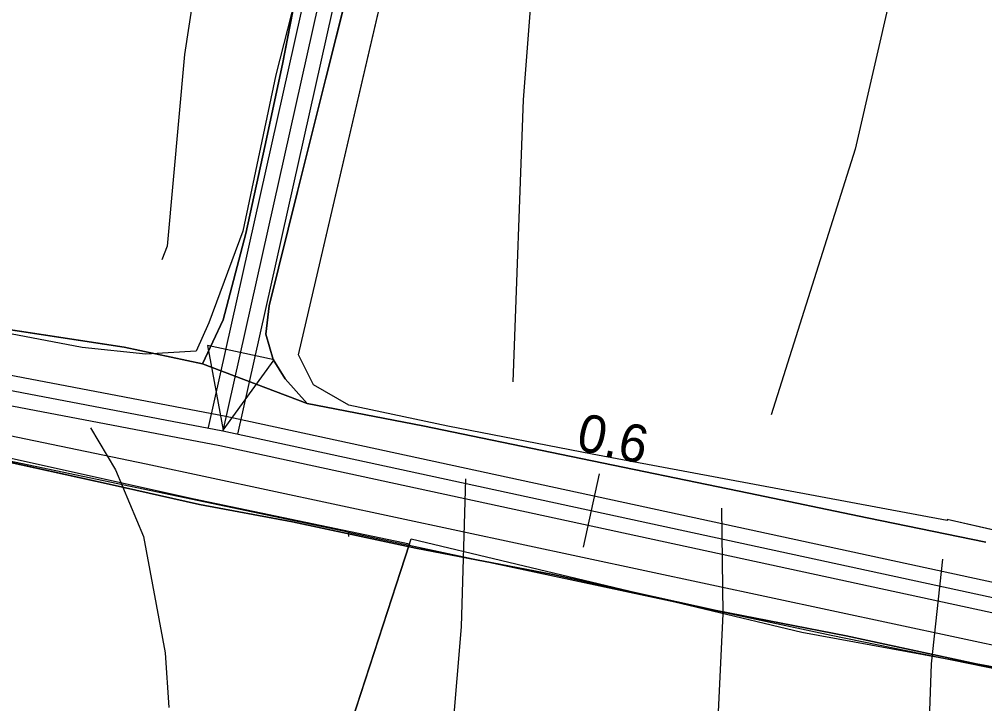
# Model space of a CAD drawing. Extents: x -662620 to -656370, y -1067090 to -1062990.
# Drawn here: x -658567.2 to -658438.7, y -1066109.2 to -1066018.1 of the extents above; entities that cross this region are included whole.
import ezdxf

# ---------------------------------------------------------------- set-up
doc = ezdxf.new("R2010")
doc.units = 0
for name, color, linetype in [('Agrotechnicka_opatreni_hrazkovani_a_dulkovani__mulcovani', 7, 'Continuous'), ('Default', 7, 'Continuous'), ('KRAJINNÁ_ZELEŇ_-_LINIOVÁ_-_STAV', 7, 'Continuous'), ('Organizacni_opatreni_ochranne_zatravnení__protierozni_rozmistovani_plodin__osevni_postup__stridani_plodin', 7, 'Continuous'), ('ORNÁ_PŮDA_-_STÁVAJÍCÍ', 7, 'Continuous'), ('OSTATNÍ_PLOCHA_-_STÁVAJÍCÍ', 7, 'Continuous'), ('OVOCNÝ_SAD_-_NAVRŽENÝ', 7, 'Continuous'), ('POLNÍ_CESTA_STÁVAJÍCÍ_-_KRAJ', 7, 'Continuous'), ('POLNÍ_CESTA_STÁVAJÍCÍ_-_OSA', 7, 'Continuous'), ('Popis_objektú_polních_cest_stávajících', 7, 'Continuous'), ('SDELOVACÍ_VEDENÍ_-_PODZEMNÍ', 7, 'Continuous'), ('VRSTEVNICE_ZDŮRAZNĚNÁ', 7, 'Continuous'), ('VRSTEVNICE_ZÁKLADNÍ', 7, 'Continuous')]:
    doc.layers.add(name, color=color, linetype=linetype)

msp = doc.modelspace()

# ---------------------------------------------------------------- linework, layer by layer
at = {"layer": 'Agrotechnicka_opatreni_hrazkovani_a_dulkovani__mulcovani'}
msp.add_lwpolyline([(-658454.8, -1065610.1), (-658459, -1065660.6), (-658461.7, -1065689.2), (-658464.3, -1065724.3), (-658468.4, -1065749), (-658474.4, -1065783.9), (-658495.1, -1065872.9), (-658497.1, -1065881.9), (-658511.2, -1065934.8), (-658524.2, -1065990.5), (-658533.1, -1066025.5), (-658537.5, -1066046.3), (-658542, -1066058.5), (-658543.7, -1066062.3), (-658550.4, -1066062.7), (-658558.89, -1066061.79), (-658593.12, -1066055.27), (-658662.77, -1066041.21), (-658696.34, -1066031.17)], dxfattribs=at)
at = {"layer": 'KRAJINNÁ_ZELEŇ_-_LINIOVÁ_-_STAV'}
msp.add_lwpolyline([(-658959.05, -1065783.35), (-658947.24, -1065797.56), (-658872.02, -1065915.68), (-658813.56, -1065971.96), (-658731.02, -1066028.63), (-658683.86, -1066049.55), (-658550.37, -1066077.32), (-658326.35, -1066125.24), (-658216.95, -1066151.9)], dxfattribs=at)
at = {"layer": 'Organizacni_opatreni_ochranne_zatravnení__protierozni_rozmistovani_plodin__osevni_postup__stridani_plodin'}
for points in [[(-658515.32, -1066087.97), (-658611.96, -1066385.11), (-658646.2, -1066373.85), (-658701.92, -1066378.35), (-658721.2, -1066377.7), (-658762.8, -1066380.1), (-658798.28, -1066383.49), (-658790.2, -1066369.8), (-658772.2, -1066340.5), (-658732.5, -1066271.9), (-658721.7, -1066265.7), (-658679.4, -1066183.2), (-658621.96, -1066065.74), (-658571.37, -1066075.89), (-658543.99, -1066081.97)], [(-658515.32, -1066087.97), (-658515.1, -1066087.3), (-658463.1, -1066099.7), (-658439.9, -1066104), (-658420, -1066108.1), (-658378.44, -1066116.48), (-658322, -1066128.5), (-658314.14, -1066130.32), (-658331.87, -1066164.3), (-658365.21, -1066192.88), (-658382.67, -1066230.98), (-658387.44, -1066253.2), (-658528.66, -1066410.12), (-658550.72, -1066405.24), (-658611.9, -1066385.13)]]:
    msp.add_lwpolyline(points, close=True, dxfattribs=at)
at = {"layer": 'ORNÁ_PŮDA_-_STÁVAJÍCÍ'}
for p, q in [((-658529.42, -1066009.61), (-658532.2, -1066024.05)), ((-658526.46, -1066025.95), (-658523.07, -1066012.44)), ((-658532.2, -1066024.05), (-658534.55, -1066035.05)), ((-658530.2, -1066041.01), (-658526.46, -1066025.95)), ((-658534.55, -1066035.05), (-658537.08, -1066046.61)), ((-658533.98, -1066056.27), (-658530.2, -1066041.01)), ((-658537.08, -1066046.61), (-658540.12, -1066058.12)), ((-658534.45, -1066060.02), (-658533.98, -1066056.27)), ((-658540.12, -1066058.12), (-658542.86, -1066064)), ((-658553.31, -1066061.76), (-658571.02, -1066059.07)), ((-658533.44, -1066063.41), (-658534.45, -1066060.02)), ((-658542.86, -1066064), (-658553.31, -1066061.76)), ((-658531.85, -1066065.98), (-658533.44, -1066063.41)), ((-658528.91, -1066069.25), (-658531.85, -1066065.98)), ((-658513.52, -1066072.22), (-658528.91, -1066069.25)), ((-658493.79, -1066076.34), (-658513.52, -1066072.22)), ((-658575.13, -1066075.64), (-658555.3, -1066080.01)), ((-658470.14, -1066081.21), (-658493.79, -1066076.34)), ((-658555.3, -1066080.01), (-658543.28, -1066082.74)), ((-658454.39, -1066084.49), (-658470.14, -1066081.21)), ((-658543.28, -1066082.74), (-658530.89, -1066085.04)), ((-658438.59, -1066087.73), (-658454.39, -1066084.49)), ((-658530.89, -1066085.04), (-658514.45, -1066088.53)), ((-658514.45, -1066088.53), (-658496.25, -1066092.03)), ((-658496.25, -1066092.03), (-658474.5, -1066096.83)), ((-658474.5, -1066096.83), (-658457.17, -1066100.19)), ((-658457.17, -1066100.19), (-658439.88, -1066103.92)), ((-658439.88, -1066103.92), (-658421.57, -1066107.33))]:
    msp.add_line(p, q, dxfattribs=at)
for points in [[(-658438.59, -1066087.73), (-658454.39, -1066084.49), (-658470.14, -1066081.21), (-658493.79, -1066076.34), (-658513.52, -1066072.22), (-658528.91, -1066069.25), (-658531.85, -1066065.98), (-658533.44, -1066063.41), (-658534.45, -1066060.02), (-658533.98, -1066056.27), (-658530.2, -1066041.01), (-658526.46, -1066025.95), (-658523.07, -1066012.44), (-658519.48, -1065997.86), (-658513.83, -1065974.83), (-658508.7, -1065953.75), (-658504.04, -1065934.75), (-658500.14, -1065918.67), (-658495.88, -1065901.4), (-658494.52, -1065895.82), (-658490.06, -1065877.58), (-658484.66, -1065855.71), (-658478.38, -1065830.32), (-658474.55, -1065814.53)], [(-658506.89, -1065918.21), (-658510.62, -1065933.53), (-658515.92, -1065953.16), (-658520.56, -1065973.53), (-658525.75, -1065993.86), (-658529.42, -1066009.61), (-658532.2, -1066024.05), (-658534.55, -1066035.05), (-658537.08, -1066046.61), (-658540.12, -1066058.12), (-658542.86, -1066064), (-658553.31, -1066061.76), (-658571.02, -1066059.07), (-658592.28, -1066054.55), (-658612.83, -1066050.63), (-658633.89, -1066046.44), (-658647.79, -1066043.35), (-658658.93, -1066040.48), (-658671.32, -1066037.87), (-658681.89, -1066034.49), (-658693.65, -1066031.42)], [(-658649.35, -1066128.19), (-658633.64, -1066100.29), (-658623.57, -1066082.05), (-658616.96, -1066067.35), (-658595.36, -1066071.95), (-658575.13, -1066075.64), (-658555.3, -1066080.01), (-658543.28, -1066082.74), (-658530.89, -1066085.04), (-658514.45, -1066088.53), (-658496.25, -1066092.03), (-658474.5, -1066096.83), (-658457.17, -1066100.19), (-658439.88, -1066103.92), (-658421.57, -1066107.33)]]:
    msp.add_lwpolyline(points, dxfattribs=at)
at = {"layer": 'OSTATNÍ_PLOCHA_-_STÁVAJÍCÍ'}
for p, q in [((-658532.2, -1066024.05), (-658529.42, -1066009.61)), ((-658532.2, -1066024.05), (-658529.42, -1066009.61)), ((-658523.07, -1066012.44), (-658526.46, -1066025.95)), ((-658523.07, -1066012.44), (-658526.46, -1066025.95)), ((-658534.55, -1066035.05), (-658532.2, -1066024.05)), ((-658534.55, -1066035.05), (-658532.2, -1066024.05)), ((-658526.46, -1066025.95), (-658530.2, -1066041.01)), ((-658526.46, -1066025.95), (-658530.2, -1066041.01)), ((-658537.08, -1066046.61), (-658534.55, -1066035.05)), ((-658537.08, -1066046.61), (-658534.55, -1066035.05)), ((-658530.2, -1066041.01), (-658533.98, -1066056.27)), ((-658530.2, -1066041.01), (-658533.98, -1066056.27)), ((-658540.12, -1066058.12), (-658537.08, -1066046.61)), ((-658540.12, -1066058.12), (-658537.08, -1066046.61)), ((-658533.98, -1066056.27), (-658534.45, -1066060.02)), ((-658533.98, -1066056.27), (-658534.45, -1066060.02)), ((-658542.86, -1066064), (-658540.12, -1066058.12)), ((-658542.86, -1066064), (-658540.12, -1066058.12)), ((-658571.02, -1066059.07), (-658553.31, -1066061.76)), ((-658571.02, -1066059.07), (-658553.31, -1066061.76)), ((-658534.45, -1066060.02), (-658533.44, -1066063.41)), ((-658534.45, -1066060.02), (-658533.44, -1066063.41)), ((-658553.31, -1066061.76), (-658542.86, -1066064)), ((-658553.31, -1066061.76), (-658542.86, -1066064)), ((-658528.91, -1066069.25), (-658542.86, -1066064)), ((-658542.86, -1066064), (-658528.91, -1066069.25)), ((-658528.91, -1066069.25), (-658542.86, -1066064)), ((-658542.86, -1066064), (-658528.91, -1066069.25)), ((-658533.44, -1066063.41), (-658531.85, -1066065.98)), ((-658533.44, -1066063.41), (-658531.85, -1066065.98)), ((-658531.85, -1066065.98), (-658528.91, -1066069.25)), ((-658531.85, -1066065.98), (-658528.91, -1066069.25)), ((-658528.91, -1066069.25), (-658513.52, -1066072.22)), ((-658528.91, -1066069.25), (-658513.52, -1066072.22)), ((-658513.52, -1066072.22), (-658493.79, -1066076.34)), ((-658513.52, -1066072.22), (-658493.79, -1066076.34)), ((-658555.3, -1066080.01), (-658575.13, -1066075.64)), ((-658555.3, -1066080.01), (-658575.13, -1066075.64)), ((-658493.79, -1066076.34), (-658470.14, -1066081.21)), ((-658493.79, -1066076.34), (-658470.14, -1066081.21)), ((-658543.28, -1066082.74), (-658555.3, -1066080.01)), ((-658543.28, -1066082.74), (-658555.3, -1066080.01)), ((-658470.14, -1066081.21), (-658454.39, -1066084.49)), ((-658470.14, -1066081.21), (-658454.39, -1066084.49)), ((-658530.89, -1066085.04), (-658543.28, -1066082.74)), ((-658530.89, -1066085.04), (-658543.28, -1066082.74)), ((-658454.39, -1066084.49), (-658438.59, -1066087.73)), ((-658454.39, -1066084.49), (-658438.59, -1066087.73)), ((-658514.45, -1066088.53), (-658530.89, -1066085.04)), ((-658514.45, -1066088.53), (-658530.89, -1066085.04)), ((-658496.25, -1066092.03), (-658514.45, -1066088.53)), ((-658496.25, -1066092.03), (-658514.45, -1066088.53)), ((-658474.5, -1066096.83), (-658496.25, -1066092.03)), ((-658474.5, -1066096.83), (-658496.25, -1066092.03)), ((-658457.17, -1066100.19), (-658474.5, -1066096.83)), ((-658457.17, -1066100.19), (-658474.5, -1066096.83)), ((-658439.88, -1066103.92), (-658457.17, -1066100.19)), ((-658439.88, -1066103.92), (-658457.17, -1066100.19)), ((-658421.57, -1066107.33), (-658439.88, -1066103.92)), ((-658421.57, -1066107.33), (-658439.88, -1066103.92))]:
    msp.add_line(p, q, dxfattribs=at)
for points in [[(-658500.14, -1065918.67), (-658504.04, -1065934.75), (-658508.7, -1065953.75), (-658513.83, -1065974.83), (-658519.48, -1065997.86), (-658523.07, -1066012.44), (-658526.46, -1066025.95), (-658530.2, -1066041.01), (-658533.98, -1066056.27), (-658534.45, -1066060.02), (-658533.44, -1066063.41), (-658531.85, -1066065.98), (-658528.91, -1066069.25), (-658542.86, -1066064), (-658540.12, -1066058.12), (-658537.08, -1066046.61), (-658534.55, -1066035.05), (-658532.2, -1066024.05), (-658529.42, -1066009.61), (-658525.75, -1065993.86), (-658520.56, -1065973.53), (-658515.92, -1065953.16), (-658510.62, -1065933.53), (-658506.89, -1065918.21)], [(-658500.14, -1065918.67), (-658504.04, -1065934.75), (-658508.7, -1065953.75), (-658513.83, -1065974.83), (-658519.48, -1065997.86), (-658523.07, -1066012.44), (-658526.46, -1066025.95), (-658530.2, -1066041.01), (-658533.98, -1066056.27), (-658534.45, -1066060.02), (-658533.44, -1066063.41), (-658531.85, -1066065.98), (-658528.91, -1066069.25), (-658542.86, -1066064), (-658540.12, -1066058.12), (-658537.08, -1066046.61), (-658534.55, -1066035.05), (-658532.2, -1066024.05), (-658529.42, -1066009.61), (-658525.75, -1065993.86), (-658520.56, -1065973.53), (-658515.92, -1065953.16), (-658510.62, -1065933.53), (-658506.89, -1065918.21)], [(-658693.65, -1066031.42), (-658681.89, -1066034.49), (-658671.32, -1066037.87), (-658658.93, -1066040.48), (-658647.79, -1066043.35), (-658633.89, -1066046.44), (-658612.83, -1066050.63), (-658592.28, -1066054.55), (-658571.02, -1066059.07), (-658553.31, -1066061.76), (-658542.86, -1066064), (-658528.91, -1066069.25), (-658513.52, -1066072.22), (-658493.79, -1066076.34), (-658470.14, -1066081.21), (-658454.39, -1066084.49), (-658438.59, -1066087.73)], [(-658693.65, -1066031.42), (-658681.89, -1066034.49), (-658671.32, -1066037.87), (-658658.93, -1066040.48), (-658647.79, -1066043.35), (-658633.89, -1066046.44), (-658612.83, -1066050.63), (-658592.28, -1066054.55), (-658571.02, -1066059.07), (-658553.31, -1066061.76), (-658542.86, -1066064), (-658528.91, -1066069.25), (-658513.52, -1066072.22), (-658493.79, -1066076.34), (-658470.14, -1066081.21), (-658454.39, -1066084.49), (-658438.59, -1066087.73)], [(-658421.57, -1066107.33), (-658439.88, -1066103.92), (-658457.17, -1066100.19), (-658474.5, -1066096.83), (-658496.25, -1066092.03), (-658514.45, -1066088.53), (-658530.89, -1066085.04), (-658543.28, -1066082.74), (-658555.3, -1066080.01), (-658575.13, -1066075.64), (-658595.36, -1066071.95), (-658616.96, -1066067.35), (-658637.32, -1066063.32), (-658653, -1066060.49), (-658664.87, -1066057.71), (-658676.79, -1066055.13), (-658689.65, -1066050.45)], [(-658421.57, -1066107.33), (-658439.88, -1066103.92), (-658457.17, -1066100.19), (-658474.5, -1066096.83), (-658496.25, -1066092.03), (-658514.45, -1066088.53), (-658530.89, -1066085.04), (-658543.28, -1066082.74), (-658555.3, -1066080.01), (-658575.13, -1066075.64), (-658595.36, -1066071.95), (-658616.96, -1066067.35), (-658637.32, -1066063.32), (-658653, -1066060.49), (-658664.87, -1066057.71), (-658676.79, -1066055.13), (-658689.65, -1066050.45)]]:
    msp.add_lwpolyline(points, dxfattribs=at)
at = {"layer": 'OVOCNÝ_SAD_-_NAVRŽENÝ'}
for p, q in [((-658530.1, -1066062.8), (-658502.8, -1065945.7)), ((-658528.1, -1066066.8), (-658530.1, -1066062.8)), ((-658523.4, -1066069.5), (-658528.1, -1066066.8)), ((-658510.2, -1066072.3), (-658523.4, -1066069.5)), ((-658491, -1066076), (-658510.2, -1066072.3)), ((-658443.76, -1066084.83), (-658491, -1066076)), ((-658443.73, -1066084.72), (-658443.76, -1066084.83)), ((-658422.63, -1066089.51), (-658443.73, -1066084.72))]:
    msp.add_line(p, q, dxfattribs=at)
msp.add_lwpolyline([(-658313.74, -1065716.61), (-658350.95, -1065883.3), (-658397.29, -1066090.9), (-658398.3, -1066095.4), (-658422.68, -1066089.69), (-658422.63, -1066089.51), (-658443.73, -1066084.72), (-658443.76, -1066084.83), (-658491, -1066076), (-658510.2, -1066072.3), (-658523.4, -1066069.5), (-658528.1, -1066066.8), (-658530.1, -1066062.8), (-658502.8, -1065945.7), (-658491.5, -1065895.8), (-658465.4, -1065787.9), (-658461.6, -1065748.9), (-658456.9, -1065690.2), (-658313.2, -1065714.2)], close=True, dxfattribs=at)
at = {"layer": 'POLNÍ_CESTA_STÁVAJÍCÍ_-_KRAJ'}
for points in [[(-658489.42, -1065109.24), (-658458.57, -1065230.06), (-658447.22, -1065313.74), (-658445.54, -1065428.7), (-658462.4, -1065715.93), (-658542.09, -1066072.48)], [(-658485.55, -1065108.25), (-658454.64, -1065229.3), (-658443.22, -1065313.45), (-658441.54, -1065428.79), (-658458.43, -1065716.49), (-658538.19, -1066073.35)], [(-658964.93, -1065765.97), (-658948.85, -1065779.68), (-658872.13, -1065898.42), (-658849.11, -1065926.97), (-658824.31, -1065951.09), (-658788.91, -1065977.64), (-658730.44, -1066020.71), (-658708.91, -1066031.66), (-658684.8, -1066040.95), (-658655.4, -1066048.88), (-658539.74, -1066070.95), (-658265.21, -1066130.39), (-658217.8, -1066142.45), (-658202.42, -1066148.63), (-658188.74, -1066156.94), (-658178.46, -1066167.89), (-658171.97, -1066180.87)], [(-658967.52, -1065769.01), (-658951.89, -1065782.34), (-658875.38, -1065900.77), (-658852.07, -1065929.66), (-658826.91, -1065954.14), (-658791.3, -1065980.85), (-658732.55, -1066024.13), (-658710.54, -1066035.32), (-658686.05, -1066044.76), (-658656.29, -1066052.78), (-658540.54, -1066074.87), (-658266.12, -1066134.28), (-658219.04, -1066146.27), (-658204.21, -1066152.22), (-658191.28, -1066160.08), (-658181.78, -1066170.2), (-658175.55, -1066182.65)]]:
    msp.add_lwpolyline(points, dxfattribs=at)
at = {"layer": 'POLNÍ_CESTA_STÁVAJÍCÍ_-_OSA'}
for points in [[(-658487.49, -1065108.74), (-658456.6, -1065229.68), (-658445.22, -1065313.6), (-658443.54, -1065428.75), (-658460.42, -1065716.21), (-658540.14, -1066072.91)], [(-658966.23, -1065767.49), (-658950.37, -1065781.01), (-658873.76, -1065899.59), (-658850.59, -1065928.31), (-658825.61, -1065952.62), (-658790.11, -1065979.25), (-658731.5, -1066022.42), (-658709.73, -1066033.49), (-658685.42, -1066042.85), (-658655.84, -1066050.83), (-658540.14, -1066072.91), (-658265.67, -1066132.34), (-658218.42, -1066144.36), (-658203.31, -1066150.43), (-658190.01, -1066158.51), (-658180.12, -1066169.05), (-658173.76, -1066181.76)], [(-658490.05, -1066078.64), (-658492.17, -1066088.41)]]:
    msp.add_lwpolyline(points, dxfattribs=at)
at = {"layer": 'Popis_objektú_polních_cest_stávajících'}
for p, q in [((-658542.18, -1066061.54), (-658540.11, -1066072.81)), ((-658537.87, -1066062.47), (-658542.18, -1066061.54)), ((-658533.31, -1066063.46), (-658537.87, -1066062.47)), ((-658540.11, -1066072.81), (-658533.31, -1066063.46))]:
    msp.add_line(p, q, dxfattribs=at)
msp.add_lwpolyline([(-658542.18, -1066061.54), (-658540.11, -1066072.81), (-658533.31, -1066063.46), (-658537.87, -1066062.47)], close=True, dxfattribs=at)
at = {"layer": 'SDELOVACÍ_VEDENÍ_-_PODZEMNÍ'}
for points in [[(-658523.47, -1066086.39), (-658575.13, -1066075.56), (-658641.14, -1066062.31), (-658677.3, -1066053.68), (-658705.12, -1066045.16), (-658742.18, -1066026.34), (-658786.34, -1065995.08), (-658823.78, -1065965.88), (-658843.22, -1065949.45), (-658870.46, -1065917.11), (-658899.93, -1065872.81), (-658935.79, -1065816.51)], [(-658523.47, -1066086.39), (-658575.13, -1066075.56), (-658641.14, -1066062.31), (-658677.3, -1066053.68), (-658705.12, -1066045.16), (-658742.18, -1066026.34), (-658786.34, -1065995.08), (-658823.78, -1065965.88), (-658843.22, -1065949.45), (-658870.46, -1065917.11), (-658899.93, -1065872.81), (-658935.79, -1065816.51)], [(-658523.47, -1066086.39), (-658575.13, -1066075.56), (-658641.14, -1066062.31), (-658677.3, -1066053.68), (-658705.12, -1066045.16), (-658742.18, -1066026.34), (-658786.34, -1065995.08), (-658823.78, -1065965.88), (-658843.22, -1065949.45), (-658870.46, -1065917.11), (-658899.93, -1065872.81), (-658935.79, -1065816.51)], [(-658523.47, -1066086.39), (-658575.13, -1066075.56), (-658641.14, -1066062.31), (-658677.3, -1066053.68), (-658705.12, -1066045.16), (-658742.18, -1066026.34), (-658786.34, -1065995.08), (-658823.78, -1065965.88), (-658843.22, -1065949.45), (-658870.46, -1065917.11), (-658899.93, -1065872.81), (-658935.79, -1065816.51)], [(-658523.47, -1066086.39), (-658575.13, -1066075.56), (-658641.14, -1066062.31), (-658677.3, -1066053.68), (-658705.12, -1066045.16), (-658742.18, -1066026.34), (-658786.34, -1065995.08), (-658823.78, -1065965.88), (-658843.22, -1065949.45), (-658870.46, -1065917.11), (-658899.93, -1065872.81), (-658935.79, -1065816.51)], [(-658523.47, -1066086.39), (-658575.13, -1066075.56), (-658641.14, -1066062.31), (-658677.3, -1066053.68), (-658705.12, -1066045.16), (-658742.18, -1066026.34), (-658786.34, -1065995.08), (-658823.78, -1065965.88), (-658843.22, -1065949.45), (-658870.46, -1065917.11), (-658899.93, -1065872.81), (-658935.79, -1065816.51)], [(-658523.47, -1066086.39), (-658459.2, -1066100.14), (-658389.94, -1066114.27), (-658304.98, -1066132.67), (-658242.8, -1066146.34), (-658226.63, -1066151.13), (-658220.22, -1066156.44), (-658216.91, -1066163.65), (-658213.26, -1066164.73), (-658209.39, -1066166.11), (-658205.27, -1066166.55), (-658199.27, -1066165.54), (-658191.21, -1066168.05), (-658186.21, -1066174.16), (-658179.82, -1066188.18), (-658171.19, -1066212.06), (-658153.94, -1066236.84), (-658128.96, -1066255.96), (-658101.29, -1066274.87), (-658070.26, -1066295.29), (-658065.34, -1066295.45), (-658064.97, -1066295.8), (-658051.49, -1066304.99)], [(-658523.47, -1066086.39), (-658523.42, -1066086.97)], [(-658523.47, -1066086.39), (-658459.2, -1066100.14), (-658389.94, -1066114.27), (-658304.98, -1066132.67), (-658242.8, -1066146.34), (-658226.63, -1066151.13), (-658220.22, -1066156.44), (-658216.91, -1066163.65), (-658213.26, -1066164.73), (-658209.39, -1066166.11), (-658205.27, -1066166.55), (-658199.27, -1066165.54), (-658191.21, -1066168.05), (-658186.21, -1066174.16), (-658179.82, -1066188.18), (-658171.19, -1066212.06), (-658153.94, -1066236.84), (-658128.96, -1066255.96), (-658101.29, -1066274.87), (-658070.26, -1066295.29), (-658065.34, -1066295.45), (-658064.97, -1066295.8), (-658051.49, -1066304.99)], [(-658523.47, -1066086.39), (-658523.42, -1066086.97)]]:
    msp.add_lwpolyline(points, dxfattribs=at)
at = {"layer": 'VRSTEVNICE_ZDŮRAZNĚNÁ'}
for points in [[(-658501.51, -1066066.37), (-658500.13, -1066028.8), (-658497.83, -1065998.7), (-658496.69, -1065990.1), (-658496.26, -1065964.3), (-658496.44, -1065943.99)], [(-658507.86, -1066079.28), (-658508.44, -1066099.02), (-658509.59, -1066112.78), (-658514.89, -1066144.88), (-658525.06, -1066181.57), (-658527.07, -1066190.74), (-658530.08, -1066213.68), (-658530.08, -1066227.43), (-658529.36, -1066236.61), (-658525.49, -1066264.12), (-658524.78, -1066278.17), (-658524.92, -1066296.51), (-658526.21, -1066305.68), (-658528.22, -1066314.86), (-658532.52, -1066328.62), (-658537.1, -1066337.79), (-658542.69, -1066346.39), (-658550.57, -1066355.56), (-658568.92, -1066373.19), (-658590.27, -1066388.95)]]:
    msp.add_lwpolyline(points, dxfattribs=at)
at = {"layer": 'VRSTEVNICE_ZÁKLADNÍ'}
for points in [[(-658546.78, -1065937.83), (-658543.55, -1065959.43), (-658542.84, -1065992.39), (-658544.12, -1066015.18), (-658545.27, -1066022.78), (-658547.57, -1066048.29), (-658548.28, -1066050.15)], [(-658546.78, -1065937.83), (-658543.55, -1065959.43), (-658542.84, -1065992.39), (-658544.12, -1066015.18), (-658545.27, -1066022.78), (-658547.57, -1066048.29), (-658548.28, -1066050.15)], [(-658443.36, -1065950.48), (-658444.81, -1065962.73), (-658445.09, -1065966.6), (-658448.1, -1065982.36), (-658449.11, -1065998.13), (-658448.82, -1066004.15), (-658455.99, -1066035.39), (-658467.16, -1066070.79)], [(-658443.36, -1065950.48), (-658444.81, -1065962.73), (-658445.09, -1065966.6), (-658448.1, -1065982.36), (-658449.11, -1065998.13), (-658448.82, -1066004.15), (-658455.99, -1066035.39), (-658467.16, -1066070.79)], [(-658557.77, -1066072.52), (-658554.44, -1066078.1), (-658550.72, -1066086.98), (-658547.85, -1066102.46), (-658547.36, -1066109.74)], [(-658557.77, -1066072.52), (-658554.44, -1066078.1), (-658550.72, -1066086.98), (-658547.85, -1066102.46), (-658547.36, -1066109.74)], [(-658473.8, -1066083.22), (-658473.61, -1066097.3), (-658474.47, -1066115.93), (-658477.63, -1066134.56), (-658485.94, -1066168.1), (-658492.82, -1066187.02), (-658493.25, -1066187.16), (-658496.54, -1066196.76), (-658498.98, -1066207.08), (-658499.98, -1066218.26), (-658500.13, -1066242.63), (-658503.28, -1066266.42), (-658505, -1066285.05), (-658507.87, -1066307.98), (-658508.58, -1066312.28), (-658512.16, -1066330.91), (-658517.47, -1066346.67), (-658522.2, -1066356.71), (-658524.78, -1066361.01), (-658535.1, -1066373.33), (-658543.7, -1066381.79), (-658564.76, -1066397.69)], [(-658473.8, -1066083.22), (-658473.61, -1066097.3), (-658474.47, -1066115.93), (-658477.63, -1066134.56), (-658485.94, -1066168.1), (-658492.82, -1066187.02), (-658493.25, -1066187.16), (-658496.54, -1066196.76), (-658498.98, -1066207.08), (-658499.98, -1066218.26), (-658500.13, -1066242.63), (-658503.28, -1066266.42), (-658505, -1066285.05), (-658507.87, -1066307.98), (-658508.58, -1066312.28), (-658512.16, -1066330.91), (-658517.47, -1066346.67), (-658522.2, -1066356.71), (-658524.78, -1066361.01), (-658535.1, -1066373.33), (-658543.7, -1066381.79), (-658564.76, -1066397.69)], [(-658444.38, -1066090), (-658445.86, -1066103.92), (-658446.1, -1066110.2), (-658450.83, -1066138.58), (-658454.27, -1066150.62), (-658460, -1066167.81), (-658480.78, -1066223.42), (-658483.07, -1066231.45), (-658485.22, -1066247.5), (-658486.37, -1066268.71), (-658489.66, -1066290.78), (-658494.54, -1066316.86), (-658500.7, -1066342.66), (-658504.71, -1066356.56), (-658509.3, -1066368.17), (-658515.89, -1066380.93), (-658524.06, -1066392.53)], [(-658444.38, -1066090), (-658445.86, -1066103.92), (-658446.1, -1066110.2), (-658450.83, -1066138.58), (-658454.27, -1066150.62), (-658460, -1066167.81), (-658480.78, -1066223.42), (-658483.07, -1066231.45), (-658485.22, -1066247.5), (-658486.37, -1066268.71), (-658489.66, -1066290.78), (-658494.54, -1066316.86), (-658500.7, -1066342.66), (-658504.71, -1066356.56), (-658509.3, -1066368.17), (-658515.89, -1066380.93), (-658524.06, -1066392.53)]]:
    msp.add_lwpolyline(points, dxfattribs=at)

# ---------------------------------------------------------------- texts
at = {"layer": 'Default'}
msp.add_text('0.6', height=5, rotation=347.7842, dxfattribs=at).set_placement((-658493.28, -1066075.38))

doc.saveas('drawing.dxf')
